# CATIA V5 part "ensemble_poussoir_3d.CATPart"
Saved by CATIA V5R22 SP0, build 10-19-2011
Part number: Part69
Bounding box of the stored display mesh (mm): x 0 to 190, y 0 to 48, z 0 to 49
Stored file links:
  C:\Users\La forge\Desktop\CAO_PER_pick&place_2023A\Sous_Ensemble_Flacon\Verin\Poussoir_Flacon\ensemble_poussoir_3d.CATPart
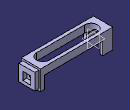
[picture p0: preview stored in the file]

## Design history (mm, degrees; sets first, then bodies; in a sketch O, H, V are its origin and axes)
Body1 (main body)
  Sketch1 on yz-plane, origin (0, 0, 0), H (0, 1, 0), V (0, 0, 1)
    line L1 (0, 0) -> (48, 0)
    line L2 (48, 0) -> (48, 49)
    line L3 (48, 49) -> (0, 49)
    line L4 (0, 49) -> (0, 0)
    point P1 (48, 0)
    point P2 (48, 49)
    point P3 (0, 49)
    distance P1 P2 = 49
    distance P2 P3 = 48
    horizontal: L1 H, L3 H
    vertical: L2 V, L4 V
  Pad1: profile Sketch1, direction (1, 0, 0), length 180
  Sketch2 on face of Pad1 from Sketch1.L4, origin (0, 0, 0), H (1, 0, 0), V (0, 0, 1)
    point P1 (25, 0)
    line L1 (25, 0) -> (170, 0)
    line L2 (170, 0) -> (170, 31)
    line L3 (170, 31) -> (25, 31)
    line L4 (25, 31) -> (25, 0)
    point P2 (170, 0)
    reference projected point E1 (180, 0) from vertex [face of Pad1 from Sketch1.L4 | end face of Pad1 | face of Pad1 from Sketch1.L1]
    reference projected line E2 (0, 49) -> (180, 49) from edge [face of Pad1 from Sketch1.L4 | face of Pad1 from Sketch1.L3]
    distance P2 E1 = 10
    distance P1 O = 25
    distance L3 E2 = 18
    coincidence: P1 H
    horizontal: L1 H, L3 H
    vertical: L2 V, L4 V
  Pocket1: profile Sketch2, direction (0, 1, 0), through (limit type 3)
  Sketch3 on start face of Pad1, origin (0, 0, 0), H (0, -1, 0), V (0, 0, 1)
    line L1 (-41, 0) -> (-7, 0)
    line L2 (-7, 0) -> (-7, 25)
    line L3 (-41, 25) -> (-41, 0)
    point P2 (-7, 0)
    point P3 (-7, 49)
    point P4 (-41, 49)
    reference projected line E1 (0, 49) -> (0, 0) from edge [start face of Pad1 | face of Pad1 from Sketch1.L4]
    reference projected line E2 (-48, 0) -> (-48, 49) from edge [start face of Pad1 | face of Pad1 from Sketch1.L2]
    reference projected line E3 (0, 0) -> (-48, 0) from edge [start face of Pad1 | face of Pad1 from Sketch1.L1]
    point P5 (-7, 25)
    point P6 (-41, 25)
    arc A1 centre (-24, 19.0839) radius 18 from (-7, 25) to (-41, 25) ccw
    point P8 (-7, 25)
    point P9 (-41, 25)
    distance L2 E1 = 7
    distance L3 E2 = 7
    length L3 = 25
    radius A1 = 18
    distance P5 P2 = 25
    horizontal: L1 H
    vertical: L2 V, L3 V
    coincidence: E3 L1, L3 P6, L2 P5, P5 P8, P6 P9
  Pocket2: profile Sketch3, direction (1, 0, 0), up to face of Pocket1 from Sketch2.L4
  Sketch4 on face of Pad1 from Sketch1.L3, origin (0, 0, 49), H (1, 0, 0), V (0, 1, 0)
    point P1 (90, 24)
    line L1 (150, 8) -> (30, 8)
    line L2 (30, 40) -> (150, 40)
    point P3 (150, 8)
    point P4 (30, 8)
    arc A1 centre (150, 24) radius 16 from (150, 40) to (150, 8) cw
    arc A2 centre (30, 24) radius 16 from (30, 8) to (30, 40) cw
    distance L1 L2 = 32
    distance P3 P4 = 120
    radius A1 = 16
    radius A2 = 16
    horizontal: L1 H, L2 H
    equidistance: L1 L2 P1
    fix: P1
  Pocket3: profile Sketch4, direction (0, 0, -1), through (limit type 3)
  Sketch5 on end face of Pad1, origin (180, 0, 0), H (0, 1, 0), V (0, 0, 1)
    circle A1 centre (24, 21) radius 4
    point P1 (24, 21)
    reference projected line E1 (48, 49) -> (0, 49) from edge [face of Pad1 from Sketch1.L3 | end face of Pad1]
    reference projected line E2 (48, 0) -> (48, 49) from edge [face of Pad1 from Sketch1.L2 | end face of Pad1]
    distance P1 E1 = 28
    distance P1 E2 = 24
    radius A1 = 4
  Pocket4: profile Sketch5, direction (-1, 0, 0), through (limit type 3)
  Sketch6 on end face of Pad1, origin (180, 0, 0), H (0, 1, 0), V (0, 0, 1)
    point P1 (24, 24.5)
    line L1 (44, 44.5) -> (44, 4.5)
    line L2 (44, 4.5) -> (4, 4.5)
    line L3 (4, 4.5) -> (4, 44.5)
    line L4 (4, 44.5) -> (44, 44.5)
    point P2 (44, 44.5)
    point P4 (4, 4.5)
    point P5 (4, 44.5)
    distance P5 P4 = 40
    distance P2 P5 = 40
    vertical: L1 V, L3 V
    horizontal: L2 H, L4 H
    equidistance: L1 L3 P1, L2 L4 P1
    fix: P1
  Pad2: profile Sketch6, direction (1, 0, 0), length 10
  Sketch7 on end face of Pad2, origin (190, 0, 0), H (0, 1, 0), V (0, 0, 1)
    point P1 (24, 22)
    line L1 (34, 32) -> (34, 12)
    line L2 (34, 12) -> (14, 12)
    line L3 (14, 12) -> (14, 32)
    line L4 (14, 32) -> (34, 32)
    point P2 (34, 32)
    point P3 (34, 12)
    reference projected line E1 (4, 4.5) -> (44, 4.5) from edge [face of Pad2 from Sketch6.L2 | end face of Pad2]
    reference projected line E2 (0, 49) -> (0, 0) from edge [face of Pad1 from Sketch1.L4 | end face of Pad1]
    distance P2 P3 = 20
    length L4 = 20
    distance P1 E1 = 17.5
    distance P1 E2 = 24
    vertical: L1 V, L3 V
    horizontal: L2 H, L4 H
    equidistance: L1 L3 P1, L2 L4 P1
  Pocket5: profile Sketch7, direction (-1, 0, 0), up to end face of Pad1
